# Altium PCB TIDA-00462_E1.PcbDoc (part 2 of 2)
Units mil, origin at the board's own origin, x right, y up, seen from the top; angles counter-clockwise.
Board outline 2300 x 2550 mil, 4 copper layers (Top Layer, MidLayer1 (GND), MidLayer2 (PWR), Bottom Layer), stack 79.8 mil thick; 106 components, 69 nets, 311 pads, 76 vias.
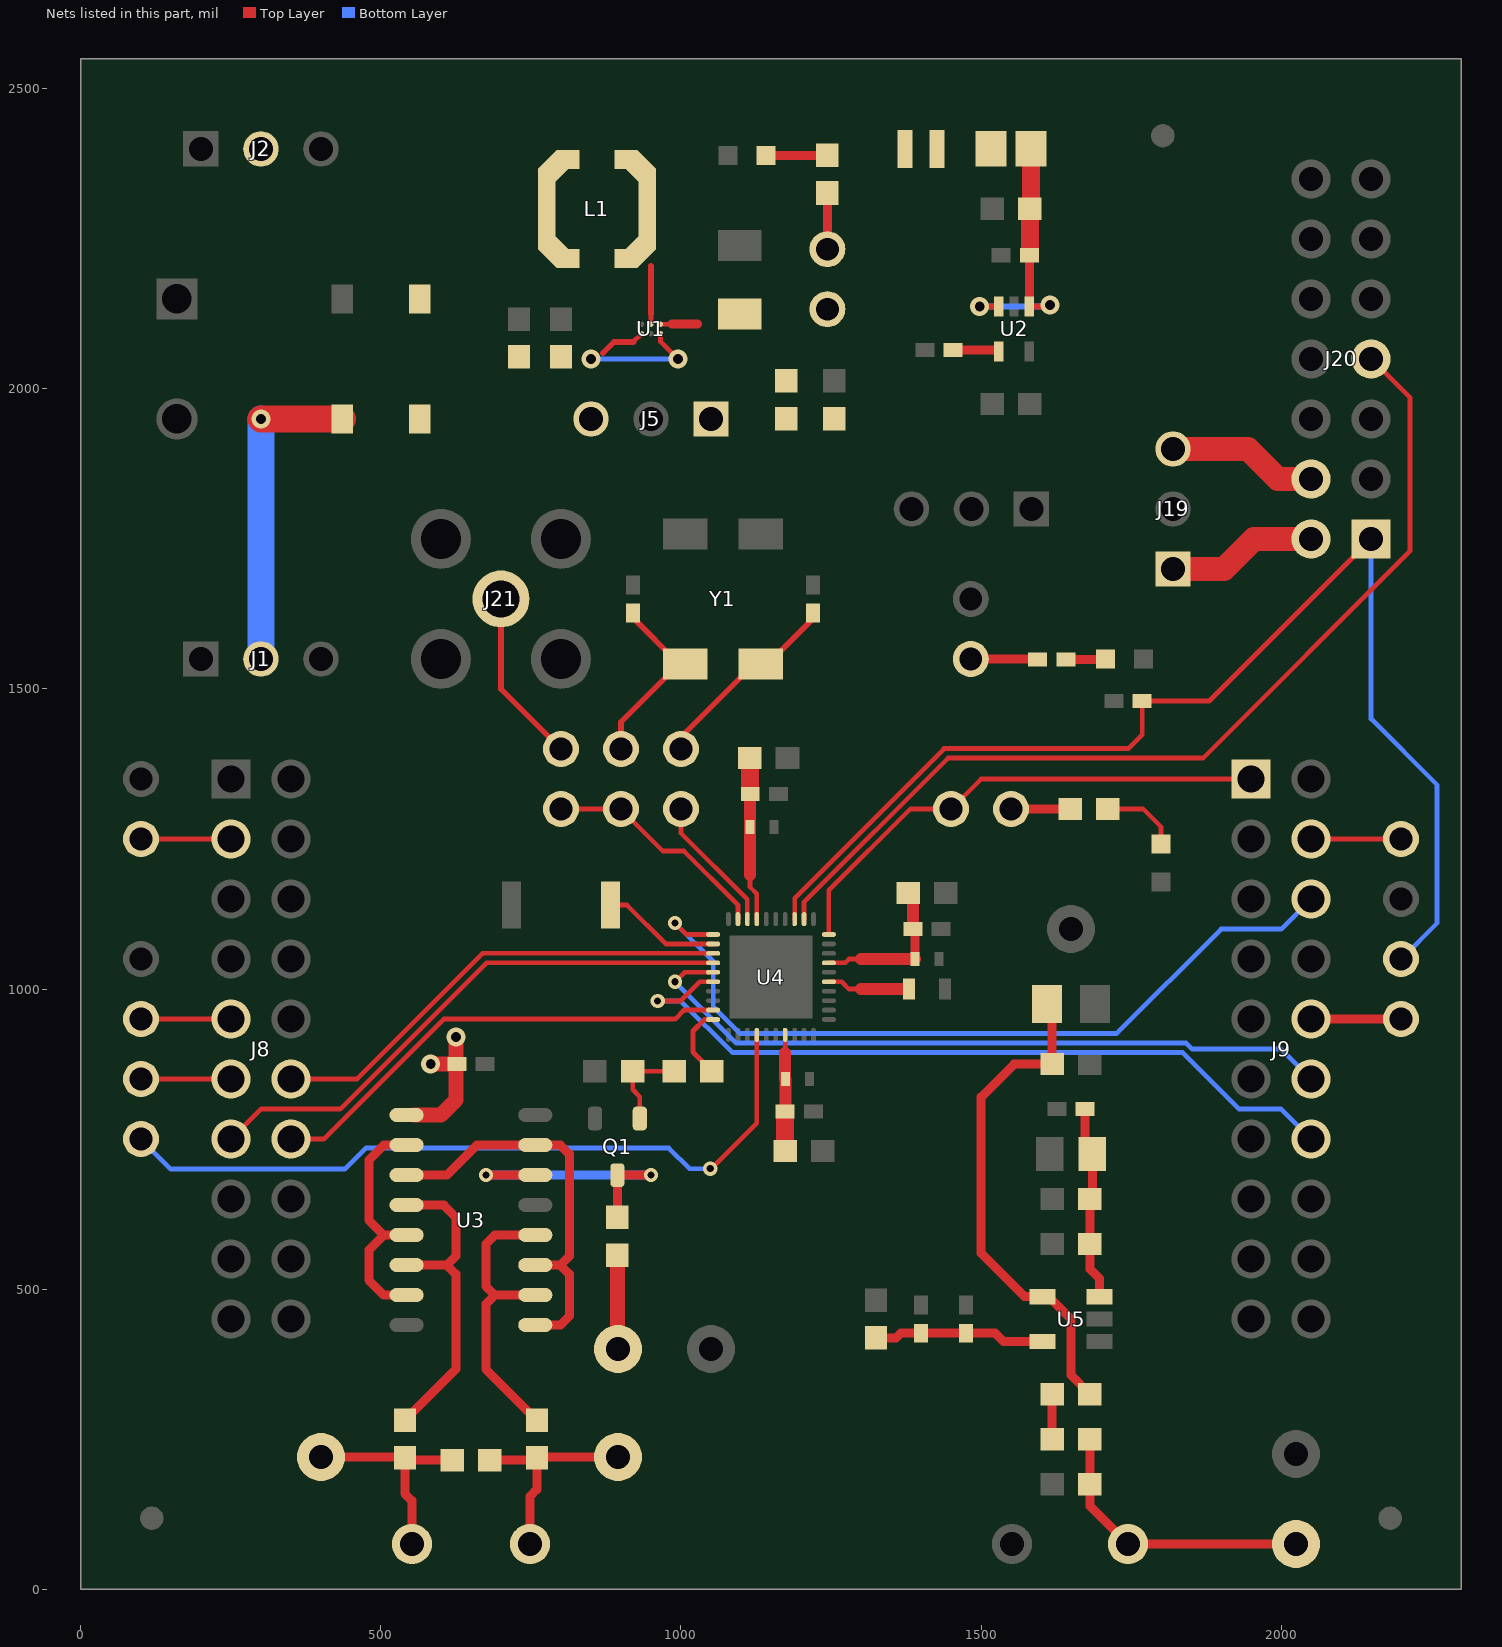
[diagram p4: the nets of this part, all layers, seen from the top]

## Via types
v1: diameter 32, hole 16, Top Layer to Bottom Layer, tented both sides, 60 vias
v2: diameter 24, hole 12, Top Layer to Bottom Layer, tented both sides, 11 vias
v3: diameter 19.68, hole 7.87, Top Layer to Bottom Layer, tented both sides, 5 vias

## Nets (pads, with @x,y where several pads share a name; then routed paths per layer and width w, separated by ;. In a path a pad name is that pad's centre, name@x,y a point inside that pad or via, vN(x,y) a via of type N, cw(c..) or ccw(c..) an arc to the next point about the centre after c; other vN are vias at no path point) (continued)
LCD_SPI_CS: J25.2 U4.14 | length 1253.4
  Top Layer w7.87: v2@1050,700 1126.38,776.38 U4.14@1126.38,923.54
  Bottom Layer w7.87: J25.2@100,750 150,700 440,700 474.89,734.89 980,734.89 1014.25,700.64 v2(1048.91,700.64)
LDO_IN: C3.1 C4.1 R1.2 U2.1 U2.3 | length 445.9
  Top Layer w10: v1(1497.6,2137.4) U2.3@1529.41,2137.4 ; U2.1@1580.59,2137.4 1612.4,2137.4 v1(1615,2140)
  Top Layer w15: U2.1@1580.59,2137.4 C4.1@1580.62,2223
  Top Layer w30: C4.1@1580.62,2223 1581.5,2223.87 C3.1@1581.5,2300 1583.46,2301.97 R1.2@1583.46,2400
  Bottom Layer w10: v1(1497.6,2137.4) v1@1612.4,2137.4
NetC7_1: C7.1 U2.4 | length 76.8
  Top Layer w15: C7.1@1453.62,2065 1527.01,2065 U2.4@1529.41,2062.6
NetC11_1: C11.1 U4.25 | length 138.6
  Top Layer w7.87: U4.25@1246.46,1012.13 1267.87,1012.13 1280,1000 1300,1000
  Top Layer w20: 1300,1000 C11.1@1380,1000
NetC12_1: C12.1 C13.1 R10.1 U4.37 | length 273.8
  Top Layer w7.87: 1115,1190 1115,1170 1126.38,1158.62 U4.37@1126.38,1116.46
  Top Layer w20: 1115,1190 C12.1@1115,1270 1115,1324.62 C13.1@1115.38,1325
  Top Layer w30: R10.1@1114.5,1385 1115.38,1384.13 C13.1@1115.38,1325
NetC14_1: C14.1 C15.1 R11.1 U4.27 | length 244.7
  Top Layer w7.87: U4.27@1246.46,1043.62 1273.62,1043.62 1280,1050 1300,1050
  Top Layer w15: C14.1@1390,1050 C15.1@1390,1096.38
  Top Layer w20: 1300,1050 C14.1@1390,1050 ; C15.1@1386.38,1100 R11.1@1386.38,1152.13
NetC16_1: C16.1 C17.1 R12.1 U4.17 | length 193.9
  Top Layer w7.87: 1173.62,893 U4.17@1173.62,923.54
  Top Layer w15: R12.1@1173.38,730.13 R12.1@1173.5,730 ; C17.1@1173.38,796 C17.1@1174,796.62
  Top Layer w20: C16.1@1173.62,850 1173.62,893 ; C17.1@1174,796.62 C16.1@1174,850
  Top Layer w30: R12.1@1173.38,730.13 C17.1@1173.38,796
NetC18_1: C18.1 C24.1 R17.1 U5.5 | length 286.7
  Top Layer w15: R17.1@1325,418.5 1358.5,418.5 1366.38,426.38 C24.1@1400,426.38 C18.1@1475,426.38 1523.62,426.38 1537.4,412.6 U5.5@1602.76,412.6
NetC19_1: C19.1 R13.1 R15.2 U5.4 | length 816.5
  Top Layer w15: U5.4@1602.76,487.4 1572.6,487.4 1500,560 1500,820 1555,875 R15.2@1618.5,875 C19.1@1618.5,966.5 ; U5.4@1612.6,487.4 1650,450 1650,356.5 R13.1@1681.5,325
NetC20_1: C20.1 J15.1 Y1.4 | length 298.2
  Top Layer w10: J15.1@900,1400 900,1445 996.73,1541.73 920,1618.46 C20.1@920,1626.38
NetC21_1: C21.1 J16.1 Y1.1 | length 331
  Top Layer w10: J16.1@1000,1400 1000,1420 1121.73,1541.73 Y1.1@1132.99,1541.73 1144.73,1541.73 1220,1617 C21.1@1220,1626.38
NetC22_1: C22.1 C23.1 R18.1 R19.2 U5.3 | length 325.6
  Top Layer w15: C23.1@1673.62,800 1673.62,736.81 C22.1@1685.43,725 1685.43,653.94 R19.2@1681.5,650 R18.1@1681.5,575 1681.5,533.5 1697.24,517.76 U5.3@1697.24,487.4
NetC25_1: C25.1 J12.1 R14.2 TP6.1 | length 481.3
  Top Layer w15: C25.1@1681.5,250 R14.2@1681.5,175 1681.5,138.5 J12.1@1745,75 TP6.1@2025,75
NetC25_2: C25.2 R13.2 | length 75
  Top Layer w15: C25.2@1618.5,250 R13.2@1618.5,325
NetD1_2: D1.2 J1.2 | length 535.5
  Top Layer w45: v1(300,1950) D1.2@435.54,1950
  Bottom Layer w45: J1.2@300,1550 v1(300,1950)
NetD3_2: D3.2 R3.1 | length 102.7
  Top Layer w15: D3.2@1141.5,2389 1141.99,2389.5 R3.1@1244,2389.5
NetD4_2: D4.2 R5.2 | length 66.3
  Top Layer w15: R5.2@1641.62,1549 1706.5,1549 D4.2@1707.5,1550
NetD5_2: D5.2 R20.1 | length 129.4
  Top Layer w7.87: R20.1@1711.5,1300 1770,1300 1800,1270 D5.2@1800,1241.5
NetJ2_2: J2.2 L2.1
NetJ3_1: J3.1 R3.2 | length 93.5
  Top Layer w15: J3.1@1244,2233 R3.2@1244,2326.5
NetJ5_1: J5.1 R2.1 R4.2
NetJ7_1: J7.1 R5.1 | length 111.8
  Top Layer w15: J7.1@1483,1550 1593.38,1550 R5.1@1594.38,1549
NetJ8_3: J8.3 J22.1 | length 150
  Top Layer w7.87: J22.1@100,1250 J8.3@250,1250
NetJ8_9: J8.9 J24.1 | length 150
  Top Layer w7.87: J24.1@100,950 J8.9@250,950
NetJ8_11: J8.11 J25.1 | length 150
  Top Layer w7.87: J25.1@100,850 J8.11@250,850
NetJ9_4: J9.4 J23.2 | length 150
  Top Layer w7.87: J9.4@2050,1250 J23.2@2200,1250
NetJ9_10: J9.10 J18.2 | length 150
  Top Layer w15: J9.10@2050,950 J18.2@2200,950
NetJ14_1: J14.1 J21.1 | length 291.4
  Top Layer w10: J21.1@700,1650 700,1500 J14.1@800,1400
NetJ14_2: J14.2 J15.2 U4.39 | length 384.8
  Top Layer w7.87: J14.2@800,1300 J15.2@900,1300 970,1230 1005,1230 1094.88,1140.12 U4.39@1094.88,1116.46
NetJ16_2: J16.2 U4.38 | length 229.4
  Top Layer w7.87: J16.2@1000,1300 1000,1260 1110.63,1149.37 U4.38@1110.63,1116.46
NetJ17_2: J17.2 R20.2 | length 98.5
  Top Layer w15: J17.2@1550,1300 R20.2@1648.5,1300
NetL1_2: L1.2 U1.B2 | length 97.1
  Top Layer w7.87: U1.B2@950,2107.87 950,2125
  Top Layer w10: 950,2125 950,2204.96
NetL2_2: L2.2 R1.1
NetQ1_1: Q1.1 R7.2 R8.1 | length 152.7
  Top Layer w7.87: R8.1@919.5,863 R7.2@988.5,863
  Top Layer w8: R8.1@919.5,863 919.5,832.5 931.4,820.6 Q1.1@931.4,784.24
NetQ1_3: Q1.3 R6.1 U3.14 | length 471
  Top Layer w15: v2(675,690) U3.14@744.49,690 ; Q1.3@893.76,690 v2(950,690) ; R6.1@894,619.5 Q1.3@894,689.76
  Bottom Layer w15: v2(675,690) v2(950,690)
NetU3_2: U3.2 U3.5 U3.7 | length 443
  Top Layer w15: U3.7@555.51,490 505,490 480,515 480,565 505,590 ; U3.5@555.51,590 505,590 ; U3.2@555.51,740 505,740 480,715 480,615 505,590
NetU3_3: U3.3 U3.9 U3.11 U3.15 | length 698
  Top Layer w15: U3.3@555.51,690 610,690 660,740 744.49,740 798.98,740 813.98,725 813.98,555 798.98,540 ; U3.9@744.49,440 798.98,440 813.98,455 813.98,525 798.98,540 ; U3.11@744.49,540 798.98,540
SBWTCK: J20.7 U4.32 | length 1627.7
  Top Layer w7.87: U4.32@1205.12,1116.46 1205.12,1145.12 1445,1385 1870,1385 2215,1730 2215,1985 J20.7@2150,2050
SBWTDIO: J18.1 J20.1 R16.1 U4.33 | length 2047.1
  Top Layer w7.87: U4.33@1189.37,1116.46 1189.37,1137.38 1189.37,1151.64 1438.48,1400.75 1745.75,1400.75 1768.62,1423.62 R16.1@1768.62,1480
  Top Layer w8: R16.1@1768.62,1480 1880,1480 J20.1@2150,1750
  Bottom Layer w7.87: J20.1@2150,1750 2150,1450 2260,1340 2260,1110 J18.1@2200,1050
SPI_CLK: J8.13 U4.4 | length 925.2
  Top Layer w7.87: J8.13@250,750 300,800 432.27,800 675.89,1043.62 U4.4@1053.54,1043.62
SPI_CS: J9.6 U4.1 | length 1345
  Top Layer w7.87: v2(990,1110) 1009.13,1090.87 U4.1@1053.54,1090.87
  Bottom Layer w7.87: v2(990,1110) 1053.54,1046.46 1053.54,970.73 1098.52,925.75 1725.75,925.75 1900,1100 2000,1100 J9.6@2050,1150
SPI_SIMO: J9.12 U4.5 | length 1197.2
  Top Layer w7.87: v2(990,1012) 1005.87,1027.87 U4.5@1053.54,1027.87
  Bottom Layer w7.87: v2(990,1012) 1092,910 1842.27,910 1852.27,900 2000,900 J9.12@2050,850
SPI_SOMI: J9.14 U4.6 | length 1290.1
  Top Layer w7.87: v2(961,980) 999,980 1031.13,1012.13 U4.6@1053.54,1012.13
  Bottom Layer w7.87: v2(961,980) 999.73,980 1085.48,894.25 1835.75,894.25 1930,800 2000,800 J9.14@2050,750
START: J8.14 U4.9 | length 792.3
  Top Layer w7.87: J8.14@350,750 404.54,750 604.54,950 990.63,950 1004.88,964.25 ; 1004.88,964.88 U4.9@1053.54,964.88
STOP: J9.1 J17.1 U4.30 | length 853.8
  Top Layer w7.87: U4.30@1246.46,1090.87 1246.46,1164.19 1382.27,1300 J17.1@1450,1300 1500,1350 J9.1@1950,1350
TRIGGER: J8.12 U4.3 | length 790.3
  Top Layer w7.87: J8.12@350,850 460,850 669.37,1059.37 U4.3@1053.54,1059.37
TRIGGER_SW: S1.1 U4.2 | length 197.7
  Top Layer w7.87: S1.1@882.68,1140 910,1140 974.88,1075.12 U4.2@1053.54,1075.12
TX: R7.1 U4.10 | length 124.4
  Top Layer w8: R7.1@1053.54,865.05 R7.1@1051.5,863 1020,894.5 1020,930 1039.07,949.07 U4.10@1053.54,949.13
US_TX_1: C10.2 U3.4 U3.6 | length 518.4
  Top Layer w15: C10.2@540,281.5 625,366.5 625,525 610,540 ; U3.6@555.51,540 610,540 ; U3.4@555.51,640 605,640 625,620 625,555 610,540
US_TX_2: C9.2 U3.10 U3.12 | length 471.3
  Top Layer w15: U3.10@744.49,490 690,490 ; U3.12@744.49,590 690,590 675,575 675,505 690,490 ; C9.2@760,281.5 675,366.5 675,475 690,490
US_TX_A: C10.1 J10.1 R9.1 TP4.1 | length 371
  Top Layer w15: TP4.1@400,220 538.5,220 C10.1@540,218.5 ; J10.1@551.57,75 551.57,147.43 540,159 C10.1@540,218.5 ; R9.1@617,218.5 R9.1@618.5,217 ; R9.1@618.5,215 543.5,215 C10.1@540,218.5
US_TX_B: C9.1 J11.1 R9.2 TP3.1 | length 359.8
  Top Layer w15: R9.2@681.5,215 756.5,215 C9.1@760,211.5 ; J11.1@748.43,75 748.43,154.43 760,166 C9.1@760,211.5 ; TP3.1@895,220 768.5,220 C9.1@760,211.5
V_IN: C1.1 C2.1 D1.1 D2.1 J5.3 L1.1 U1.A1 U1.C1 | length 276.8
  Top Layer w7.87: 920.47,2078.35 U1.A1@934.25,2092.13 ; U1.C1@965.75,2092.13 965.75,2079.25 v1(995,2050)
  Top Layer w10: 870,2060 888.35,2078.35 920.47,2078.35
  Bottom Layer w8: v1(850,2050) v1(995,2050)
V_OUT: C6.1 C8.1 J3.2 R2.2 R6.2 TP1.1 U1.C2 U3.1 | length 448.7
  Top Layer w7.87: U1.C2@965.75,2107.87 985,2107.87
  Top Layer w15: 985,2107.87 1027.87,2107.87
  Top Layer w25: U3.1@555.51,790 600,790 625,815 625,873.62 C8.1@626.38,875 ; v1(582.76,875) C8.1@626.38,875 ; v1(625,920) 625,876.38 C8.1@626.38,875 ; R6.2@894,556.5 894,401 TP1.1@895,400
VCC_TARGET: J19.3 J20.4 | length 250.7
  Top Layer w40: J19.3@1820,1900 1945,1900 1995,1850 J20.4@2050,1850
VCC_TOOL: J19.1 J20.2 | length 250.7
  Top Layer w40: J19.1@1820,1700 1905,1700 1955,1750 J20.2@2050,1750
pads on no net: FID1.1 FID2.1 FID3.1 J8.5 J8.6 J8.7 J8.8 J8.10 J8.15 J8.16 J8.17 J8.18 J8.19 J8.20 J9.3 J9.5 J9.7 J9.8 J9.9 J9.11 J9.13 J9.15 J9.16 J9.17 J9.18 J9.19 J9.20 J20.3 J20.5 J20.6 J20.8 J20.10 J20.11 J20.13 SH-J1.0 SH-J2.0 SH-J5.0 SH-J6.0 SH-J19.0 U3.13 U3.16 U4.7 U4.8 U4.11 U4.15 U4.16 U4.19 U4.20 U4.21 U4.23 U4.24 U4.28 U4.29 U4.31 Y1.2 Y1.3

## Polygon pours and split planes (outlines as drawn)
+3.3V on Top Layer "Top Layer-No Net 7" (solid, pour order 23): 1450,1835 1445,1830 1445,1620 1450,1615 1640,1615 1650,1615 1800,1765 1850,1765 1855,1770 1855,1830 1850,1835 1450,1835
NetL2_2 on Top Layer "Top Layer-No Net 6" (solid, pour order 22): 1410,2365 1410,2435 1545,2435 1545,2365 1410,2365
GND on Top Layer "Top Layer-VUSB" (solid, remove dead copper, pour order 17): 1015,2200 1165,2200 1170,2205 1170,2325 1165,2330 1015,2330 1010,2325 1010,2205
V_OUT on Top Layer "Top Layer-No Net 5" (solid, pour order 21): 1150,1990 1200,1990 1200,2095 1205,2100 1275,2100 1280,2105 1280,2160 1275,2165 1015,2165 1010,2160 1010,2100 1015,2095 1145,2095 1150,2090 1150,1990
GND on Top Layer "Top Layer-No Net 4" (solid, pour order 20): 710,2095 905,2095 910,2100 910,2145 905,2150 715,2150 710,2145 710,2095
V_IN on Top Layer "Top Layer-No Net 2" (solid, pour order 18): 835,2365 815,2365 795,2345 795,2255 815,2235 835,2235 835,2195 590,2195 585,2190 585,2075 880,2075 885,2070 885,1920 880,1915 545,1915 540,1920 540,2400 545,2405 835,2405
NetL1_2 on Top Layer "Top Layer-No Net 3" (solid, pour order 19): 885,2405 885,2365 905,2365 925,2345 925,2255 905,2235 885,2235 885,2195 945,2195 955,2195 960,2200 960,2400 955,2405 885,2405
NetJ2_2 on Top Layer "Top Layer-No Net 1" (solid, pour order 15): 1390,2365 1360,2365 1355,2370 1355,2445 1350,2450 335,2450 330,2445 330,2370 325,2365 270,2365 265,2370 265,2495 270,2500 1385,2500 1390,2495 1390,2365
EXT_PWR on Top Layer "Top Layer-No Net" (solid, pour order 14): 125,2110 120,2115 120,2430 125,2435 230,2435 235,2430 235,2180 240,2175 455,2175 455,2115 450,2110 125,2110
NetJ5_1 on Top Layer "Top Layer-VUSB" (solid, remove dead copper, pour order 16): 1019,1982 1086,1982 1087,1982 1094,1975 1095,1974 1181,1974 1295,1974 1300,1969 1300,1903 1295,1898 1017,1898 1012,1903 1012,1977 1017,1982
V_OUT on MidLayer2 (PWR) "MidLayer2 (PWR)-No Net" (solid, pour order 24): 1105,335 1100,330 430,330 425,335 425,2295 430,2300 1333,2300 1336,2297 1336,1786 1330,1780 1110,1780 1105,1775
+3.3V on MidLayer2 (PWR) "Top Layer-VUSB" (solid, remove dead copper, pour order 26): 1875,1855 1880,1850 1880,335 1875,330 1150,330 1150,1695 1155,1700 1420,1700 1430,1710 1430,1849 1436,1855
GND on MidLayer1 (GND) "Top Layer-VUSB" (solid, remove dead copper, pour order 25): 0,2550 2300,2550 2300,0 0,0

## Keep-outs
Keep-Out Layer:
  the board outline again, w11.81
  text ".Layer_Name" at 764,-871 h60
Multi-Layer:
  circle w4: c1803,2422 r42.19
  circle w4: c2181.89,118.11 r42.19
  circle w4: c118.11,118.11 r42.19

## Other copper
Top Layer:
  text ".Layer_Name" at 736,-853 h60
MidLayer1 (GND):
  text ".Layer_Name" at 736,-853 h60
MidLayer2 (PWR):
  text ".Layer_Name" at 719,-860 h60
Bottom Layer:
  text ".Layer_Name" at 778,-860 h60

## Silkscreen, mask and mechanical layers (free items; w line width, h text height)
Top Overlay:
  circle w6: c492.38,790 r7.62
  circle w6: c931.4,818 r8.41
  circle w6: c700,1650 r159.25
  circle w6: c927,2065 r5
  circle w6: c1580.59,2179 r9.62
  circle w6: c1698,386 r7.28
  circle w6: c520,1650 r7.07
  lines w7: 398.42,1250 493.94,1250 493.94,1210 ; 433.94,1210 553.94,1210 ; 453.94,1190 533.94,1190 ; 473.94,1170 513.94,1170 ; 990,300 1110,300 ; 1010,280 1090,280 ; 1030,260 1070,260 ; 1050,300 1050,340 ; 1885,205 1885,245 ; 1905,185 1905,265 ; 1925,165 1925,285 ; 1925,225 1965,225 ; 2100,1350 2140,1350 ; 2140,1290 2140,1410 ; 2160,1310 2160,1390 ; 2180,1330 2180,1370
  text ".PRJ_Number" at 489,2465 h40
  text ".PCB_Rev" at 902,2464 h40
  text "+" at 35,2280 h40
  text "BP1" at 205,1415 h25
  text "BP21" at 315,1415 h25
  text "BP40" at 1900,1415 h25
  text "BP20" at 2015,1415 h25
  text "BP10" at 200,360 h25
  text "BP30" at 310,360 h25
  text "BP31" at 1905,360 h25
  text "BP11" at 2020,360 h25
  text ".Layer_Name" at 659,-864 h60
Bottom Overlay:
  lines w6: 166,1369 166,1332 185,1351 167,1369 ; 1867,1366 1867,1329 1886,1348 1868,1366
  text ".Layer_Name" at 666,-853 h60
Top Paste:
  text ".Layer_Name" at 827,-853 h60
Bottom Paste:
  text ".Layer_Name" at 925,-850 h60
Top Solder:
  text ".Layer_Name" at 820,-860 h60
Bottom Solder:
  text ".Layer_Name" at 1016,-864 h60
Drill Guide:
  text ".Layer_Name" at 967,-853 h60
M1 Board Outline:
  the board outline again, w11.81
M2 Board Dimensions:
  rectangle: 0,-275 125,-150
  rectangle: 125,-400 500,-275
  lines w7: 0,-275 1000,-275 ; 125,-400 125,-150 ; 250,-400 250,-150 ; 500,-400 500,-150 ; 750,-400 750,-150 ; 0,-400 1000,-400 1000,-150 0,-150 0,-400
M3 3D STEP Top:
  text ".Layer_Name" at 806,-864 h60
M4 3D STEP Bottom:
  text ".Layer_Name" at 743,-867 h60
M5 Assembly Top:
  circle w6: c728.38,2298 r7.62
  circle w6: c1580,2173 r5.41
  circle w4: c1126,1561 r5.66
  circle w4: c932,796 r5.66
  lines w10: -292,-930.17 6308,-930.17 ; -292,-726.83 6310,-726.83 ; -292,-523.5 -292,-1133.5 3713,-1133.5 6310,-1133.5 6310,-523.5 -291.5,-523.5 -291.5,-1133.5 1284,-1133.5 ; 2173,-1133.5 2173,-523.5 ; 3440,-726.83 3440,-523.5 ; 4280,-726.83 4280,-523.5 ; 4902,-1140 4902,-937.17
  text "COMPONENTS MARKED 'DNP' SHOULD NOT BE POPULATED." at 1153.5,-318.5 h35
  text "ASSEMBLY VARIANT:" at 1153,-434 h35
  text ".VariantName" at 2189,-434 h35
  text "SVN REV:" at 4410,-655 h35
  text "PCB VIEWED FROM TOP SIDE" at -228.5,-655.67 h35
  text "BOARD #:" at 2248,-655.67 h35
  text ".PRJ_Number" at 2793.5,-655.67 h35
  text "REV:" at 3638,-655.67 h35
  text ".PCB_Rev" at 3929.5,-655.67 h35
  text ".VersionControl_RevNumber" at 4890,-660 h35
  text ".Layer_Name" at 638,-857 h35
  text "LAYER NAME =" at -231,-863 h35
  text "PLOT NAME=" at -228.5,-1064.34 h35
  text "TEXAS INSTRUMENTS" at 5113,-1064.34 h35
  text ".plot_File_Name" at 376,-1068 h35
  text "GENERATED    :" at 2714.5,-1068 h35
  text ".Print_Date" at 3584,-1068 h35
  text ".Print_Time" at 4313,-1068 h35
M6 Assembly Bottom:
  circle w6: c173,1356 r12.37
  circle w6: c1873,1354 r13.04
  lines w10: -292.5,-727.33 6309.5,-727.33 ; -290.5,-930.67 6309.5,-930.67 ; 1115.5,-1140.5 1115.5,-937.67 ; 1737.5,-727.33 1737.5,-524 ; 2577.5,-727.33 2577.5,-524 ; 3844.5,-1134 3844.5,-524 ; 4733.5,-1134 6309,-1134 6309,-524 -292.5,-524 -292.5,-1134 2304.5,-1134 6309.5,-1134 6309.5,-524
  text "COMPONENTS MARKED 'DNP' SHOULD NOT BE POPULATED." at 6102,-318 h60
  text ".VariantName" at 5058,-434 h60
  text "ASSEMBLY VARIANT:" at 6097,-434 h60
  text ".VersionControl_RevNumber" at 1035.5,-656.17 h60
  text "SVN REV:" at 1541.5,-656.17 h60
  text ".PCB_Rev" at 2088,-656.17 h60
  text "REV:" at 2379.5,-656.17 h60
  text ".PRJ_Number" at 3224,-656.17 h60
  text "BOARD #:" at 3769.5,-656.17 h60
  text "PCB VIEWED FROM BOTTOM SIDE" at 6246,-656.17 h60
  text ".Layer_Name" at 1721,-864 h60
  text "LAYER NAME =" at 2507,-868 h60
  text "TEXAS INSTRUMENTS" at 904.5,-1064.84 h60
  text "PLOT NAME =" at 6246,-1064.84 h60
  text ".Print_Time" at 1752,-1066 h60
  text ".Print_Date" at 2481,-1066 h60
  text "GENERATED    :" at 3350.5,-1066 h60
  text ".plot_File_Name" at 5589,-1068 h60
M9 Title Sheet:
  drawing of 56 lines, arcs and shapes, not listed
  text "1" at 739.84,8036.5 h45
  text "2" at 3235.5,8036.5 h45
  text "3" at 5724.84,8036.5 h45
  text "4" at 8231.51,8036.5 h45
  text "5" at 10730.5,8036.5 h45
  text "6" at 13235.5,8036.5 h45
  text "A" at -416.5,6893.5 h45
  text "A" at 14383.5,6893.5 h45
  text "B" at -416.5,4513.5 h45
  text "B" at 14383.5,4513.5 h45
  text "C" at -416.5,2138.5 h45
  text "C" at 14383.5,2138.5 h45
  text "PROJECT TITLE:" at 11343.5,277.5 h45
  text ".PRJ_Title" at 11393.5,144.17 h45
  text "DESIGNED FOR:" at 11343.5,-23.5 h45
  text ".PRJ_Customer" at 11393.5,-163.5 h45
  text "D" at -416.5,-231.5 h45
  text "D" at 14383.5,-231.5 h45
  text "FILE NAME:" at 11343.5,-323.5 h45
  text ".PCB_File_Name_No_Path" at 11393.5,-443.5 h45
  text "Texas Instruments (TI) and/or its licensors do not warrant the accuracy or completeness of this specification" at 6374,-605.34 h45
  text "ENGINEER:" at 11343.5,-613.5 h45
  text "LAYOUT BY:" at 12848.5,-613.5 h45
  text "or any information contained therein. TI and/or its licensors do not warrant that this design will meet" at 6329.01,-718 h45
  text ".PRJ_Engineer" at 11393.5,-768.49 h45
  text ".PCB_Layout" at 12899,-768.49 h45
  text "the specifications, will be suitable for your application or fit for any particular purpose, or will operate in" at 6329.01,-830.67 h45
  text "ALTIUM DESIGNER VERSION:" at 12848.5,-923.5 h45
  text "an implementation. TI and/or its licensors do not warrant that the design is production worthy. You should" at 6329.01,-943.33 h45
  text "completely validate and test your design implementation to confirm the system functionality for your application." at 6374,-1056 h45
  text ".print_Scale" at 11393.5,-1056.83 h45
  text ".Application_BuildNumber" at 12899,-1056.83 h45
  text "1" at 739.84,-1263.5 h45
  text "2" at 3235.5,-1263.5 h45
  text "3" at 5724.84,-1263.5 h45
  text "4" at 8231.51,-1263.5 h45
  text "5" at 10730.5,-1263.5 h45
  text "6" at 13235.5,-1263.5 h45
M10 Fab Notes:
  drawing of 228 lines, arcs and shapes, not listed
  text "DESIGN INFORMATION" at 12301.13,6274 h60
  text "(REFER ALSO ARRAY/PANEL PROFILING INFORMATION)" at 12053.59,6134.29 h60
  text "BOARD SIZE" at 11367.59,6130 h60
  text "2550.00MIL" at 12495,6005 h60
  text "X" at 12335.59,6002.18 h60
  text "2300.00MIL" at 11770,6000 h60
  text "4" at 12836.13,5884 h60
  text "Number of Layers :" at 11736.13,5868 h60
  text "7.874" at 12688,5761 h60
  text "MIN. TRACK WIDTH:" at 11736.96,5754.37 h60
  text "MIL" at 12987.96,5754.37 h60
  text "MIN. CLEARANCE:" at 11736.96,5622.37 h60
  text "6.693" at 12685,5621 h60
  text "MIL" at 13004,5618 h60
  text "MIN. VIA PAD SIZE:" at 11736.96,5490.37 h60
  text "19.685" at 12644,5490 h60
  text "MIL" at 12987.96,5490.37 h60
  text "0.149mm (5.905MIL)" at 12431.96,5348.66 h60
  text "MINIMUM ANNULAR RING" at 11407.73,5344.37 h60
  text "EXTERNAL" at 13295,5343 h60
  text "PER" at 11607.73,5226.37 h60
  text "IPC-D-275 CLASS 2 LEVEL C" at 11827.73,5226.37 h60
  text "MIL, HOLES" at 13315.96,5114.08 h60
  text "+/-" at 12923.5,5113.37 h60
  text "+/-" at 13777.5,5113.37 h60
  text "REGISTRATION TOLERANCES:" at 11407.73,5108.37 h60
  text "METAL" at 12607.5,5108.37 h60
  text "5" at 13183.7,5108.37 h60
  text "3" at 14016.7,5108.37 h60
  text "MIL" at 14132.96,5108.37 h60
  text "MATERIAL:" at 11332.96,4963.91 h60
  text "FR-4 High Tg" at 12319.4,4823.58 h60
  text "FR-408" at 11753.96,4815.01 h60
  text "OTHER" at 13241.96,4815.01 h60
  text "X" at 12162.13,4808 h60
  text "63 MIL (1.6mm) +/-10%" at 12074.06,4652.29 h60
  text "THICKNESS:" at 11407.73,4648.01 h60
  text "X" at 11945.9,4648.01 h60
  text "OTHER" at 13358.96,4648.01 h60
  text "TOLERANCE:" at 11407.73,4490.01 h60
  text "X" at 12247.03,4490.01 h60
  text "ANSI IPC-6012 TYPE 3 CLASS 2" at 12433.98,4490.01 h60
  text "OTHER +/-" at 12433.96,4334.01 h60
  text "BOW & TWIST:" at 11407.73,4177.01 h60
  text "X" at 12247.03,4177.01 h60
  text "ANSI IPC-6012 TYPE 3 CLASS 2" at 12433.98,4177.01 h60
  text "OTHER +/-" at 12433.96,4018.5 h60
  text "COPPER THICKNESS (FINISHED):" at 11330,3900 h60
  text "1.4MIL (1oz)" at 12148.46,3798.92 h60
  text "2MIL (1.4oz)" at 12915.46,3798.92 h60
  text "2.8MIL (2oz)" at 13642.46,3798.92 h60
  text "OUTER:" at 11625.46,3794.64 h60
  text "X" at 12020,3794 h60
  text "1.4MIL (1oz)" at 12153.46,3641.92 h60
  text "2.8MIL (2oz)" at 12920.46,3641.92 h60
  text "N/A" at 13647,3642.29 h60
  text "INNER SIGNAL:" at 11341.38,3637.64 h60
  text "X" at 12025,3637 h60
  text "DRILLING:" at 11345,3515 h60
  text "X" at 12075.96,3438.01 h60
  text "AS SHOWN" at 12262.96,3438.01 h60
  text "X" at 12976.96,3438.01 h60
  text "NC_DRILL FILES" at 13113.96,3438.01 h60
  text "REFERENCE:" at 11520,3420 h60
  text "PTH MIN COPPER THICKNESS:" at 11427.73,3280.01 h60
  text "X" at 12777.96,3280.01 h60
  text "1MIL" at 12914.96,3280.01 h60
  text "OTHER" at 13411.96,3280.01 h60
  text "BOARD FINISH:" at 11332.96,3196.01 h60
  text "X" at 12946.96,3083.01 h60
  text "SILKSCREEN:" at 11488.18,3078.01 h60
  text "X" at 12436.96,3078.01 h60
  text "TOP" at 12562.96,3078.01 h60
  text "BOTTOM" at 13073.96,3078.01 h60
  text "SILKSCREEN COLOR:" at 11488.18,2911.01 h60
  text "X" at 12435.92,2911.01 h60
  text "WHITE" at 12562.96,2911.01 h60
  text "OTHER" at 13073.96,2911.01 h60
  text "SOLDER RESIST COLOR:" at 11488.18,2741.01 h60
  text "X" at 12055.92,2581.81 h60
  text "GREEN" at 12182.96,2581.81 h60
  text "BLUE" at 12773.96,2581.81 h60
  text "OTHER" at 13311.96,2581.81 h60
  text "IMMERSION GOLD (ENIG)" at 12423.96,2433.29 h60
  text "ENEPIG" at 13761.5,2430.01 h60
  text "SURFACE FINISH:" at 11362.96,2429.01 h60
  text "X" at 12237.01,2429.01 h60
  text "IMM. TIN/SILVER OR EQUIV" at 11692.5,2272.01 h60
  text "OTHER" at 13123.96,2272.01 h60
  text "ARRAY/PANEL:" at 11357.96,2138.01 h60
  text "CUT AND TRIM PER MECH LAYER 1" at 12418.96,2133.72 h60
  text "N.C. ROUTE" at 12418.96,1982.01 h60
  text "X" at 13097.96,1982.01 h60
  text "V. SCORE" at 13284.96,1982.01 h60
  text "CERTIFICATION:" at 11357.96,1845.01 h60
  text "MATERIALS AND WORKMANSHIP FOR ALL PCBS" at 12082.96,1845.01 h60
  text "TO MEET OR EXCEED THE REQUIREMENTS OF:" at 12082.96,1747.01 h60
  text "X" at 11709.46,1610.51 h60
  text "ANSI IPC-A-600F CLASS ->" at 11848.46,1610.51 h60
  text "X" at 13487.52,1610.51 h60
  text "2" at 13606.46,1610.51 h60
  text "1" at 13291.46,1609.01 h60
  text "3" at 13960.46,1609.01 h60
  text "X" at 11711.52,1451.01 h60
  text "UL 94V-0" at 11848.46,1451.01 h60
  text "X" at 12523.52,1451.01 h60
  text "RoHS" at 12660.46,1451.01 h60
  text "OTHER" at 13304.86,1451.01 h60
  text "PER ORDER" at 13701.92,1451.01 h60
  text "ADDITIONAL REQUIREMENTS:" at 11357.96,1310.01 h60
  text "NO" at 13694.58,1298.54 h60
  text "VIA TENTING" at 12609.13,1289 h60
  text "X" at 13178.85,1286.83 h60
  text "YES" at 13293.11,1283.44 h60
  text "IMPEDANCE CONTROL:" at 12567.13,1159 h60
  text "MICROSECTION:" at 11444.73,1158.01 h60
  text "YES" at 12350.46,1158.01 h60
  text "YES" at 13535.13,1158 h60
  text "X" at 14093.13,1151 h60
  text "NO" at 13926.6,1140.69 h60
  text "REQUIRED" at 13199.96,987.86 h60
  text "BARE BOARD ELEC. TEST:" at 11432.73,985.01 h60
  text "NONE" at 12738.46,985.01 h60
  text "X" at 13072.96,985.01 h60
  text "PER ORDER" at 13791.96,985.01 h60
  text "MANUFACTURER'S UL:" at 11432.73,828.01 h60
  text "RAIL" at 12598.46,823.72 h60
  text "METAL" at 13090.27,823.72 h60
  text "SILK" at 13601.96,823.72 h60
  text "X" at 13465.5,823.37 h60
M11 Gerber Information:
  lines w10: -292,-930.17 6308,-930.17 ; -292,-726.83 6310,-726.83 ; -292,-523.5 -292,-1133.5 3713,-1133.5 6310,-1133.5 6310,-523.5 -291.5,-523.5 -291.5,-1133.5 1284,-1133.5 ; 2463,-1133.5 2463,-523.5 ; 3585,-726.83 3585,-523.5 ; 4280,-726.83 4280,-523.5 ; 4902,-1140 4902,-937.17
  text "BOARD #:" at 2495,-655 h60
  text "ALL ARTWORK VIEWED FROM TOP SIDE" at -228.5,-655.67 h60
  text "REV:" at 3638,-655.67 h60
  text ".PCB_Rev" at 3929.5,-655.67 h60
  text "SVN REV:" at 4476,-655.67 h60
  text ".VersionControl_RevNumber" at 4982,-655.67 h60
  text ".PRJ_Number" at 2980,-660 h60
  text "LAYER NAME=" at -228.5,-858.49 h60
  text ".plot_File_Name" at 385,-1060 h60
  text "GENERATED    :" at 2580.5,-1060 h60
  text ".Print_Date" at 3450,-1060 h60
  text ".Print_Time" at 4179,-1060 h60
  text "PLOT NAME=" at -228.5,-1064.34 h60
  text "TEXAS INSTRUMENTS" at 5113,-1064.34 h60
M12 Stackup:
  lines w8: 11406.13,7425.5 14076.13,7425.5 ; 11406.13,7577 14076.13,7577 ; 11346.13,6458 ccw(c11395.13,6458) 11395.13,6409 14087.13,6409 ccw(c14087.13,6458) 14136.13,6458 14136.13,7710 ccw(c14087.13,7710) 14087.13,7759 11395.13,7759 ccw(c11395.13,7710) 11346.13,7710 11346.13,6458
  text "The Stackup Legend below this is static." at 11540,7878 h45
  text "If you change the stackup, update the Legend." at 11484,7794 h45
  text "Layer Stack Up Detail for: TIDA-00462.Pcb" at 11410,7650 h40
  text "Layer" at 11406.13,7520.5 h45
  text "Gerber" at 12360.86,7520.5 h45
  text "Copper" at 12842.88,7520.5 h45
  text "Dielectric" at 13382.04,7520.5 h45
  text "Name" at 11406.13,7450.5 h45
  text "Document" at 12360.86,7450.5 h45
  text "Thickness" at 12842.88,7450.5 h45
  text "Material" at 13382.04,7450.5 h45
  text "Top Solder Mask" at 11406.13,7351.19 h45
  text "(.GTS)" at 12360.86,7351.19 h45
  text "Solder Resist" at 13382.04,7351.19 h45
  text "Top Layer" at 11406.13,7210.56 h45
  text "(.GTL)" at 12360.86,7210.56 h45
  text "1.4mil" at 12842.88,7210.56 h45
  text "FR-4 High Tg" at 13382.04,7140.25 h45
  text "MidLayer1 (GND)" at 11406.13,7069.94 h45
  text "(.G1)" at 12360.86,7069.94 h45
  text "1.4mil" at 12842.88,7069.94 h45
  text "FR-4 High Tg" at 13382.04,6999.62 h45
  text "MidLayer2 (PWR)" at 11406.13,6929.31 h45
  text "(.G2)" at 12360.86,6929.31 h45
  text "1.4mil" at 12842.88,6929.31 h45
  text "FR-4 High Tg" at 13382.04,6859 h45
  text "Bottom Layer" at 11406.13,6788.69 h45
  text "(.GBL)" at 12360.86,6788.69 h45
  text "1.4mil" at 12842.88,6788.69 h45
  text "Bottom Solder Mask" at 11406.13,6648.06 h45
  text "(.GBS)" at 12360.86,6648.06 h45
  text "Solder Resist" at 13382.04,6648.06 h45
M13 Component Bodies Top:
  text ".Layer_Name" at 659,-860 h60
M14 Component Bodies Bottom:
  text ".Layer_Name" at 635,-864 h60
M15 Courtyards Top:
  text ".Layer_Name" at 736,-853 h60
M16 Courtyards Bottom:
  text ".Layer_Name" at 645,-853 h60
Drill Drawing:
  text ".legend" at 3337,897 h60
  text "Drill Table" at 3347,727 h60
  text "DRILL TOLERANCE" at 3341.72,613.52 h60
  text "FOR PTH +/- 3MIL" at 3342.14,504.09 h60
  text "7.874mil drill:+0/-7.874mil" at 3336,390 h60
  text "12mil drill:+0/-12mil" at 3333,277 h60
  text "16mil drill:+0/-16mil" at 3335,169 h60
  text ".Layer_Name" at 858,-846 h60

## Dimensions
0,2550 to 2300,2550 on M2 Board Dimensions
0,2550 to 0,0 on M2 Board Dimensions
0,-400 to 1000,-400 on M2 Board Dimensions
